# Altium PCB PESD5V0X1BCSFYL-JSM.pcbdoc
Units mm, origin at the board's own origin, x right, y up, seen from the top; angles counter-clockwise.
Board outline 13.86 x 13.33 mm, 2 copper layers (Top Layer, Bottom Layer), stack 0.07 mm thick; 1 components, 0 nets, 2 pads, 0 vias.
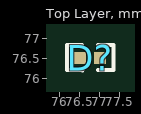
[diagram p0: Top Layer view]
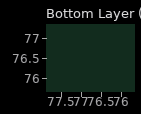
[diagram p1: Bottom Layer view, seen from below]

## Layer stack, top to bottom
Top Solder Mask Layer: solder mask 0.01, Dk 3.3
Top Layer: signal copper 0.035
Bottom Layer: signal copper 0.035
Bottom Solder Mask Layer: solder mask 0.01, Dk 3.3

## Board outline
83.71,69.85 69.85,69.85 69.85,83.18 83.71,83.18

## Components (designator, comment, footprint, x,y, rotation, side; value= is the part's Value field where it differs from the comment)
D? "PESD5V0X1BCSFYL-JSM" DFN0603-2L-BI 76.78,76.51 r0 top

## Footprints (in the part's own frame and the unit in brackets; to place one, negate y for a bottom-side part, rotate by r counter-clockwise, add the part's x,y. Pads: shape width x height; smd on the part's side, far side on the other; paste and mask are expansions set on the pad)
DFN0603-2L-BI [mm]
  rect 0.3x0.3 smd paste+0 mask+0.051: 1(-0.25,0) 2(0.25,0)
  silkscreen extent -0.58,-0.31 0.58,0.32

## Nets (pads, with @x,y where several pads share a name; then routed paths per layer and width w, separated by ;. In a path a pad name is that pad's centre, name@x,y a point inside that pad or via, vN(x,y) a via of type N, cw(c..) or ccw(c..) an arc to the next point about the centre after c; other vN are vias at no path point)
pads on no net: D?.1 D?.2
